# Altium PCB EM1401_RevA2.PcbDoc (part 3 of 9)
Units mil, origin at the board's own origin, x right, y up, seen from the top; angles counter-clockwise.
Board outline 7800 x 5300 mil, 6 copper layers (Top Layer, MidLayer1, MidLayer2, MidLayer3, MidLayer4, Bottom Layer), stack 16.8 mil thick; 751 components, 531 nets, 2554 pads, 1388 vias.
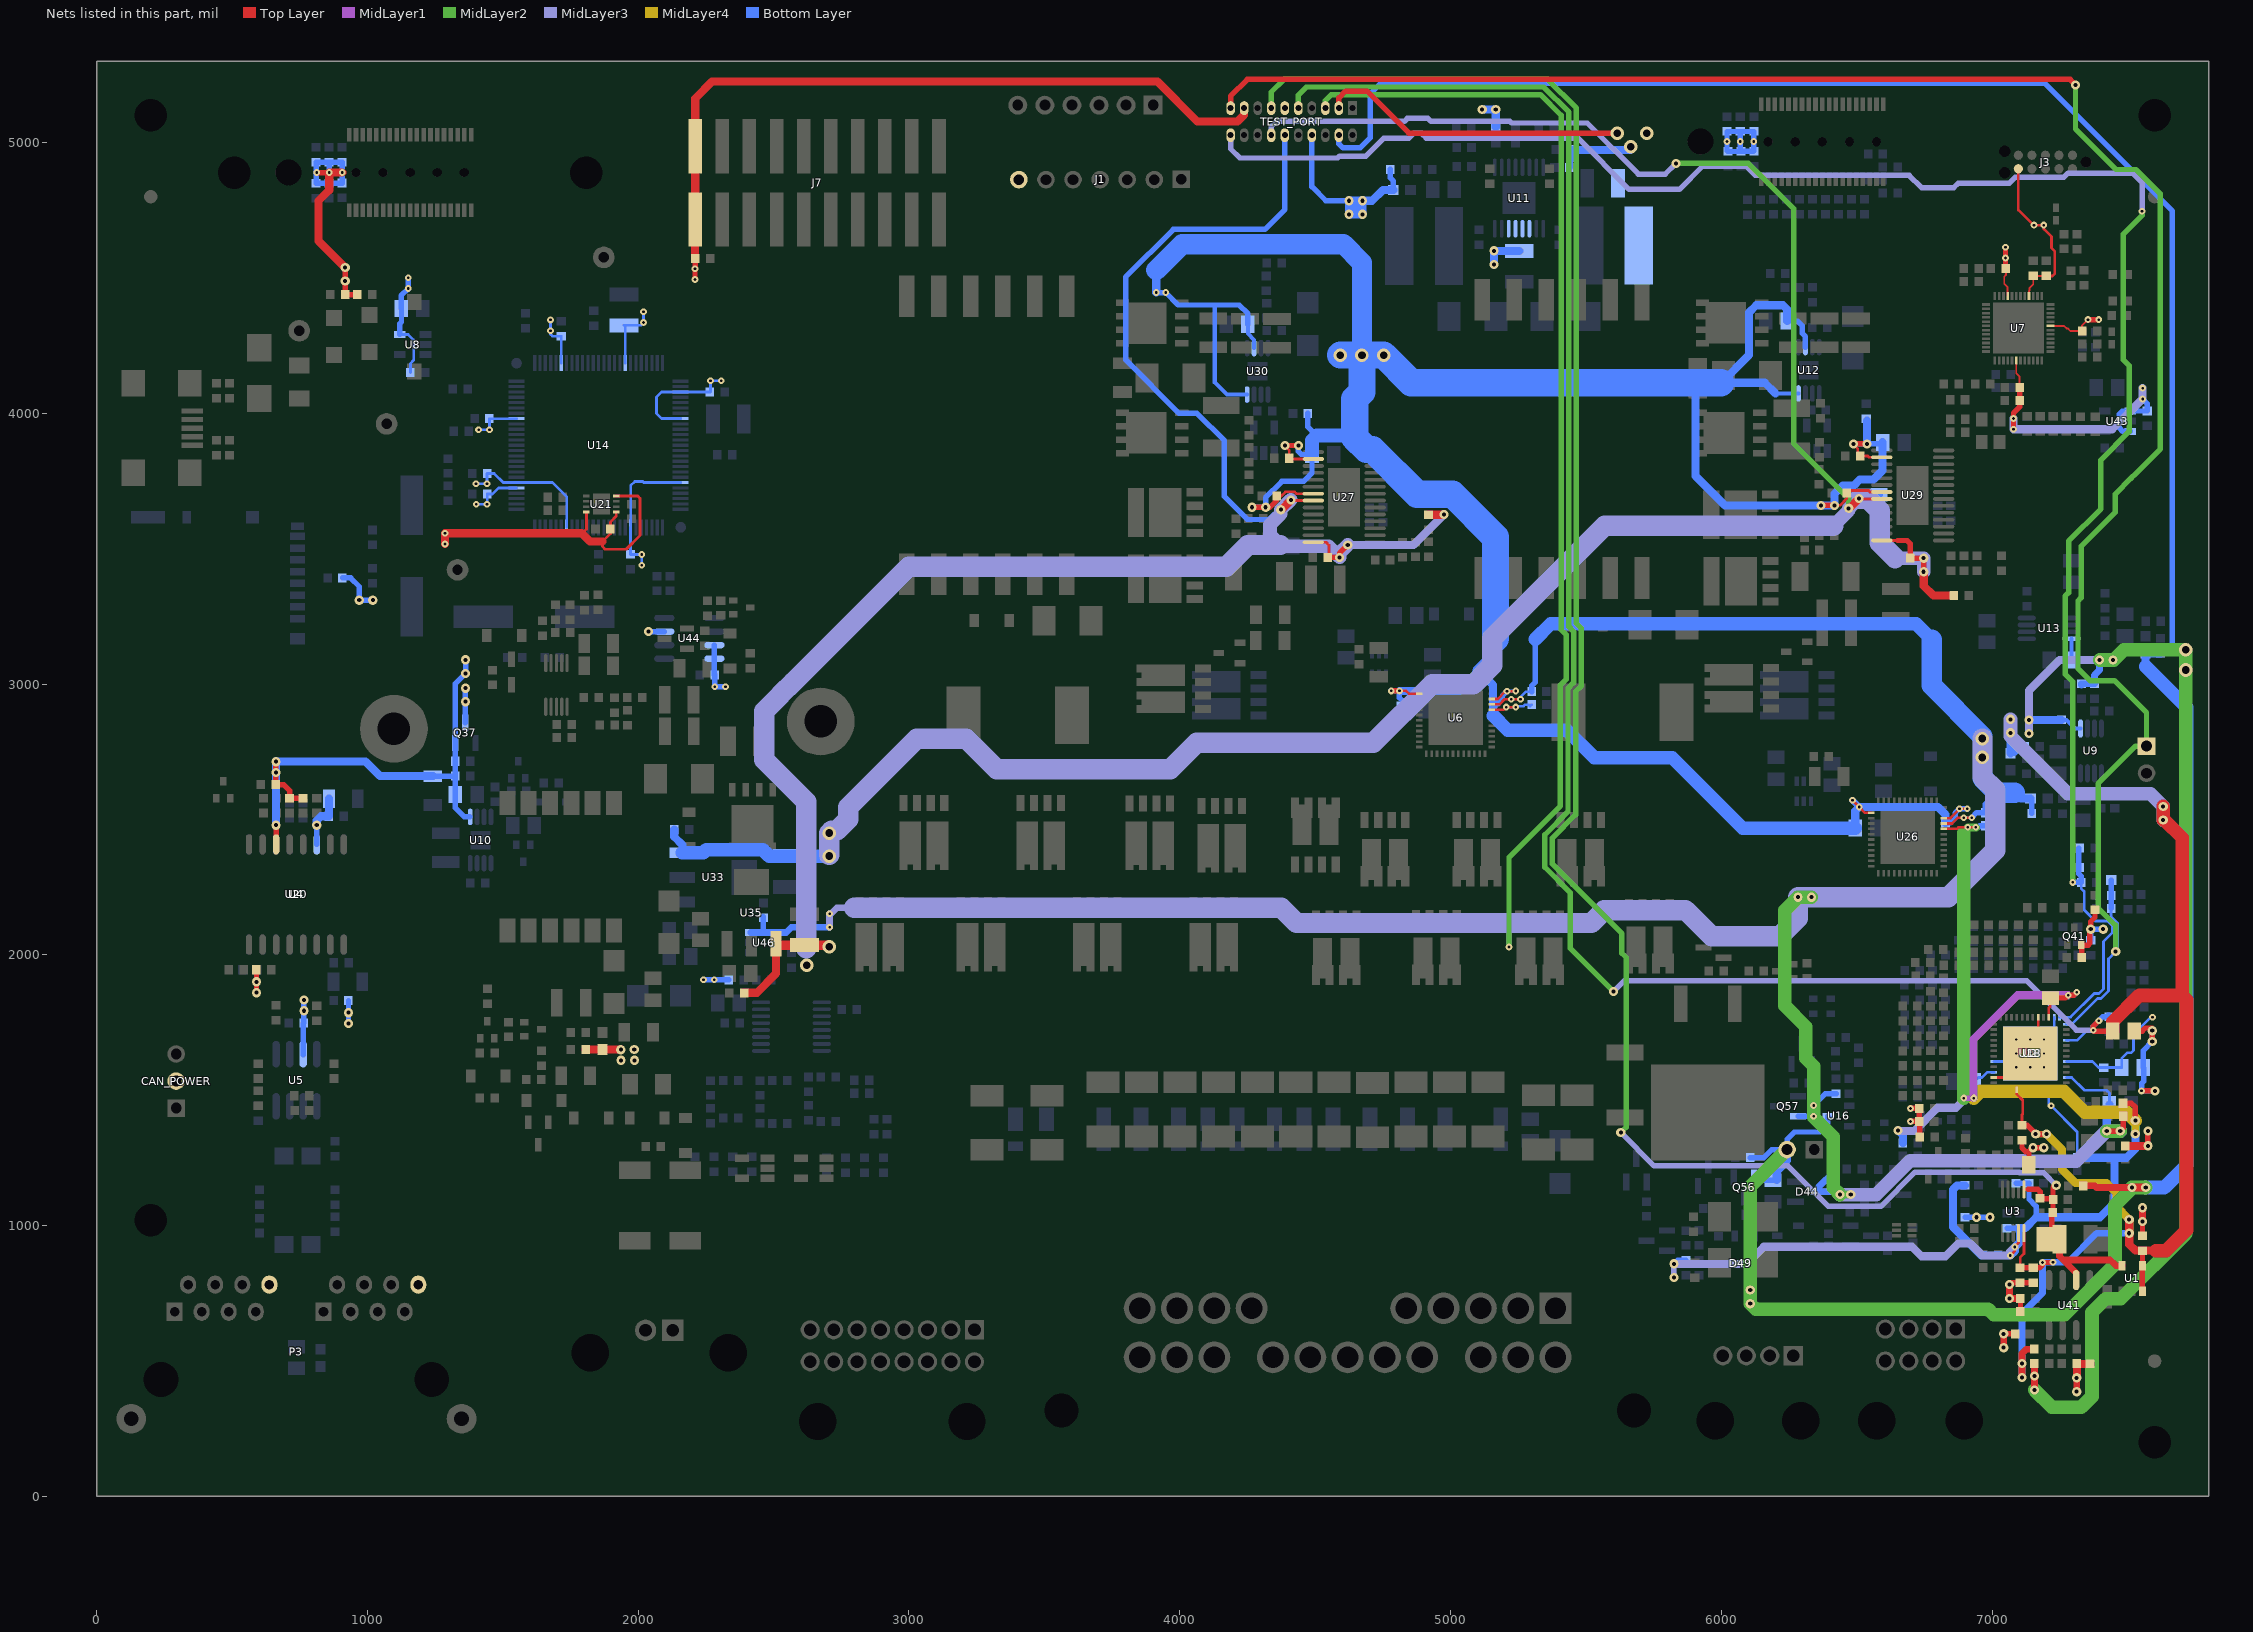
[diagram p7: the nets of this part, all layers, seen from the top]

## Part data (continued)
U21: "40MHz Dual Clock Buffer"
U24 U28: "IC INVERTER WITH SCHMITT TRIGGER SINGLE"
U27 U29: "PWM Controller"
U31: "8-Channel, 500 kSPS to 1 MSPS, 12-Bit A/D Converter"
U33 U35: "500 mA Low Dropout Regulator"
U34: "100V Current Mode PWM Controller"
U41: "IC PREC VREF 2.5V SOIC8"
U43: "Micropower 150 mA Low-Noise Ultra Low-Dropout Regulator, 5-pin SOT-23"
U44: library part 25LC512, "IC EEPROM 512KBIT 20MHZ"
Y1: library part "HC/49US - 4.194304MHz", "SMD Low Profile Crystal"
Y2: library part "HC/49US - 8MHz", "SMD Low Profile Crystal"
Zener1 Zener2: "Diode, Zener, 30V, 550mW, SMB"

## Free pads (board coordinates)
  round 50 smd: 0(7600,500) 1(200,4800) 2(7600,4800)

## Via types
v1: diameter 25, hole 10, Top Layer to Bottom Layer, tented both sides, 275 vias
v2: diameter 16, hole 8, Top Layer to Bottom Layer, tented both sides, 240 vias
v3: diameter 34, hole 15, Top Layer to Bottom Layer, tented both sides, 158 vias
v4: diameter 34, hole 15, Top Layer to Bottom Layer, 154 vias
v5: diameter 34, hole 15, Top Layer to Bottom Layer, tented top, 95 vias
v6: diameter 34, hole 15, Top Layer to Bottom Layer, tented bottom, 89 vias
v7: diameter 25, hole 10, Top Layer to Bottom Layer, tented bottom, 75 vias
v8: diameter 25, hole 10, Top Layer to Bottom Layer, 62 vias
v9: diameter 28, hole 8, Top Layer to Bottom Layer, tented both sides, 60 vias
v10: diameter 24, hole 8, Top Layer to Bottom Layer, 53 vias
v11: diameter 25, hole 10, Top Layer to Bottom Layer, tented top, 28 vias
v12: diameter 50, hole 28, Top Layer to Bottom Layer, 28 vias
v13: diameter 25, hole 8, Top Layer to Bottom Layer, tented both sides, 18 vias
v14: diameter 50, hole 28, Top Layer to Bottom Layer, tented top, 12 vias
v15: diameter 25, hole 8, Top Layer to Bottom Layer, tented top, 9 vias
v16: diameter 20, hole 8, Top Layer to Bottom Layer, tented both sides, 9 vias
v17: diameter 24, hole 8, Top Layer to Bottom Layer, tented bottom, 4 vias
v18: diameter 24, hole 8, Top Layer to Bottom Layer, tented top, 4 vias
v19: diameter 28, hole 10, Top Layer to Bottom Layer, tented both sides, 3 vias
v20: diameter 35, hole 14, Top Layer to Bottom Layer, 3 vias
v21: diameter 50, hole 28, Top Layer to Bottom Layer, tented both sides, 2 vias
v22: diameter 50, hole 28, Top Layer to Bottom Layer, tented bottom, 2 vias
v23: diameter 30, hole 14, Top Layer to Bottom Layer, tented top, 2 vias
v24: diameter 28, hole 10, Top Layer to Bottom Layer, 1 vias
v25: diameter 35, hole 14, Top Layer to Bottom Layer, tented both sides, 1 vias
v26: diameter 35, hole 14, Top Layer to Bottom Layer, tented top, 1 vias

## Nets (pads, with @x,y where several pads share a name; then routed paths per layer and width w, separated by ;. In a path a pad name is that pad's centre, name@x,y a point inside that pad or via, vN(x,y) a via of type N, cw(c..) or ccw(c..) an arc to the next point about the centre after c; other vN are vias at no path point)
+3V3: C1.2 C6.1 C15.2 C19.2 C40.2 C50.2 C63.1 C68.2 C80.2 C89.2 C99.2 C103.2 C111.2 C112.2 C115.2 C120.2 C201.2 C202.2 C203.2 C204.2 C214.2 C236.1 J1.7 J3.6 L8.2 Q37.3 R24.2 R47.2 R50.1 R51.2 R52.2 R81.1 R84.1 R104.1 R115.1 R117.1 R119.1 R121.1 R154.1 R193.1 R200.1 R209.1 R225.1 R234.1 TEST_PORT.8 U2.3 U3.9 U4.14 U6.32 U7.6 U7.19 U7.28 U7.33 U18.3 U18.38 U18.39 U18.40 U21.1 U21.4 U21.8 U26.32 U43.1 U43.3 | length 13743.6
  Top Layer w7: C203.2@7050.56,4534 7051,4533.56 7051,4511 7045,4505 7045,4478 7057.63,4465.37 U7.33@7057.63,4434.09 U7.33@7058,4434.46 ; U7.6@7089.13,4195.91 7089.13,4147.87 7101.56,4135.44 C201.2@7101.56,4095 ; C40.2@7101.56,4047.44 C40.2@7102,4047 ; U7.28@7136,4434.09 7136,4451.36 7138,4453.36 7138,4462.61 7152,4476.61 C214.2@7152,4508 7152.56,4507.44 C204.2@7200,4507.44 ; U7.19@7216.09,4322.87 7216.72,4322.24 7266.06,4322.24 7275.06,4313.24 7279.97,4313.24 7289.21,4304 C202.2@7332.44,4304 7332.44,4324.44 v1(7354,4346)
  Top Layer w10: 1792.44,3555.56 1808.88,3572.01 U21.8@1808.88,3635.47 ; U21.1@1919.12,3635.47 1919.12,3620.12 1897.56,3598.56 C115.2@1897.56,3573 1897.56,3555.56 1868,3526 1868,3508 1878,3498 1956,3498 2007,3549 2007,3686 1998.47,3694.53 U21.4@1919.12,3694.53 ; U6.32@5152.77,2905.77 5196.77,2905.77 v8(5206,2915) v1(5241,2915) ; U26.32@6821.77,2465.53 6870.53,2465.53 6876,2471 v1(6910,2471) v1(6940,2471) ; v1(7067,890) 7084,907 v1(7084,921) 7084,922 7097.89,935.89 U3.9@7097.89,972.42 ; J3.6@7097,4903 7097,4750.46 7152.46,4695 v1(7155,4695) v1(7191,4695) 7191,4681 7219.5,4652.5 7219.5,4610.17 7231,4598.67 7231,4515 7223.44,4507.44 C204.2@7200,4507.44 ; U2.3@7209.59,1769.78 7209.59,1803.59 7215,1809 7215,1840.24 C1.2@7215.41,1840.65
  Top Layer w20: v1(813,4889) v1(859,4889) ; v4(918,4539) v4(918,4489) R47.2@918,4438 R52.2@962.88,4438 ; v1@7049,4573.56 7049.56,4573 C203.2@7049.56,4534 ; v1(7049.56,4573.56) v1(7049.56,4613.56) ; v1(7079,3941) v1(7079,3981) 7079,4001 7102,4024 C40.2@7102,4047 ; C40.2@7101.56,4047.44 C201.2@7101.56,4095 ; C1.2@7215.41,1840.65 7270.65,1840.65 v1(7281,1851) 7302,1851 v1(7313,1862) ; v1(7354,4346) v1(7394,4346) ; R50.1@7483.53,1452 7514.82,1452 7529,1437.82 v3(7529,1388)
  Top Layer w30: v1(907,4889) v1(859,4889) 859,4824 820,4785 820,4637 v4(918,4539) ; v1(1287,3517) v1(1287,3557) 1791,3557 1792.44,3555.56 1822,3526 1868,3526
  MidLayer2 w20: v1(6895,1471) v1(6932,1471)
  MidLayer2 w30: 6895,2451 6910,2466 v1(6910,2471) v1(6940,2471)
  MidLayer2 w50: v1(6895,1471) 6895,2451
  MidLayer3 w20: v3(5825,809) v3(5825,859) ; v1(6895,1471) v1(6932,1471)
  MidLayer3 w30: v3(5825,859) 6094,859 6157,922 6704,922 6739,887 6828,887 6875,934 6921,934 6965,890 v1(7067,890) 7067,904 v1(7084,921) ; v3(6653,1351) 6654.5,1349.5 6713.12,1349.5 6799.12,1435.5 6866.12,1435.5 6895,1464.38 v1(6895,1471) ; v1(7079,3981) v1(7079,3941) 7444,3941 v1(7556,4053) v1(7556,4093)
  MidLayer4 w30: v1(6895,1471) v1(6932,1471) ; v3(7529,1338) v3(7529,1388)
  MidLayer4 w50: v1(6932,1471) 6957,1496 7265,1496 7342,1419 7498,1419 v3(7529,1388)
  MidLayer1 w20: v1(6895,1471) v1(6932,1471) ; v1(7281,1851) 7302,1851 v1(7313,1862)
  MidLayer1 w30: v1(6932,1471) 6932,1688.52 7094.48,1851 v1(7281,1851)
  Bottom Layer w10: v8(5206,2915) v1(5241,2915) 5244.5,2918.5 5269.5,2918.5 5275,2924 5288.42,2924 5293.92,2918.5 C19.2@5299.42,2924 ; v8@5209,2918 v8@5209.5,2918.5 ; v1(6910,2471) v1(6940,2471) ; C68.2@6934.42,1533 6948.87,1547.46 6963,1547.46 6982.57,1567.03 U18.3@7006.84,1567.03 ; U18.40@7189.91,1502.07 U18.39@7209.59,1502.07 ; U18.38@7229.28,1502.07 U18.39@7209.59,1502.07 ; R121.1@7314.12,1251 7314.12,1346.88 v11(7218,1443) 7209.59,1451.41 U18.39@7209.59,1502.07
  Bottom Layer w20: U4.14@813,2408.04 v5(813,2479) ; C63.1@908,3392 938,3392 970,3360 v3(970,3310) v3(1020,3310) ; v3@1359.6,2987.4 v3(1362,2985) v3(1362,2935) Q37.3@1362,2857.4 ; v8(2241,1908) v8(2281,1908) R104.1@2335.3,1908 ; TEST_PORT.8@4488,5027 4488,4837 4540,4785 v4(4625,4785) ; C89.2@4777.79,4901 4777.79,4869.21 4789.01,4857.99 L8.2@4789.01,4825 ; v3(5825,809) v3(5825,859) 5838.14,872.14 R51.2@5869.53,872.14 ; C111.2@6021,4969.12 v1(6021,5004) C112.2@6021,5040.88 R225.1@6070,5040.88 ; C111.2@6024,4967 6071.88,4967 R209.1@6072,4967.12 ; v1(6895,1471) v1(6932,1471) ; v1@6933,1472 v1(6932,1471) ; C68.2@6934.74,1532.68 C68.2@6934.42,1533 6932,1530.58 v1(6932,1471) ; v1(6940,2471) 6949,2471 6955,2477 C120.2@6974.29,2476.98 ; C6.1@7055,991 C236.1@7103,991 ; R117.1@7088.42,1156.88 7136.3,1156.88 R119.1@7136.42,1157 ; R119.1@7137.73,1155.68 R119.1@7136.42,1157 ; 7163,1031 7163,1071 7136.42,1097.58 R119.1@7136.42,1157 ; U43.3@7510.24,3933.6 7482.4,3933.6 7470,3946 7470,3997 7481.4,4008.4 U43.1@7510.24,4008.4 7510.4,4008.56 C99.2@7573,4008.56 7573,4036 v1(7556,4053) v1(7556,4093) ; R84.1@859,4850.12 906.56,4850.12 R81.1@907,4850.56 v1(907,4889) R193.1@907,4926.88 R154.1@859,4926.88 ; R84.1@859,4850.12 858.88,4850 C103.2@811,4850 811,4887 v1(813,4889) 811,4889 C50.2@811,4927 858.88,4927 R154.1@859,4926.88 ; R84.1@859,4850.12 v1(859,4889) R154.1@859,4926.88 ; R225.1@6070,5040.88 v1(6070,5004) 6070,4969.12 R209.1@6072,4967.12 ; R225.1@6070,5040.88 R234.1@6120,5040.88 v1(6120,5004) 6120,4969.12 6118,4967.12 R209.1@6072,4967.12
  Bottom Layer w30: v5(813,2479) 813,2496 829,2512 C80.2@858,2512 C15.2@858,2577 ; L8.2@4789.01,4825 4750,4825 4710,4785 v4(4675,4785) ; v3(6653,1351) 6655,1351 6670.88,1335.12 R24.2@6670.88,1305 ; R115.1@6900.42,1148.88 6870.88,1148.88 6855.42,1133.42 6855.42,1004.43 6855.15,1004.16 6855.15,994.85 6960,890 v1(7067,890) 7084,907 v1(7084,921) 7103,940 C236.1@7103,991 7123,991 7163,1031 7399,1031 7452,1084 7452,1250 7453,1251 ; R121.1@7314.12,1251 7453,1251 ; v3(7529,1388) v3(7529,1338) 7529,1284 7496,1251 7453,1251 ; 4625,4760 4675,4760 ; 4625,4760 v4(4625,4785) v4(4675,4785) ; 4625,4760 v4(4625,4735) v4(4675,4735) 4675,4760 ; 4675,4760 v4(4675,4785)
+3V3_LP: C29.1 C30.1 C31.1 C32.1 C33.2 C36.1 C41.1 C43.2 C44.2 C58.1 C60.1 C229.2 J7.1 J7.2 Q37.2 R44.1 R65.1 R67.1 R150.2 R151.1 R159.1 TEST_PORT.17 U8.5 U10.1 U14.3 U14.8 U14.20 U14.32 U14.44 U14.55 U14.56 U14.68 U14.81 U14.93 U20.14 U44.3 U44.7 U44.8 | length 7647.1
  Top Layer w10: v11(2209.88,4534) v11@2210.44,4534.56
  Top Layer w20: v5(662.12,2713.56) v5(662.12,2673.56) R67.1@662.12,2629 690.5,2629 713,2606.5 R151.1@713,2579.12 R159.1@763,2579.12 ; U20.14@663,2408.04 v5(663,2479) ; v1(1151,4461) v1@1151,4462 ; v11(2209.88,4494) v11(2209.88,4534) ; v11@2210.44,4534.56 C33.2@2210.44,4572
  Top Layer w30: C33.2@2210.44,4572 2210.44,4715.44 J7.1@2211,4716 J7.2@2211,4986 2211,5163 2273,5225 3917.53,5225 4064.53,5078 4214,5078 4238,5102 TEST_PORT.17@4238,5127
  Bottom Layer w10: U8.5@1119.76,4291.4 1150.6,4291.4 1171,4271 1171,4196 1159,4184 R65.1@1159,4151 ; v7(1401.44,3740) v7(1441.44,3740) 1442,3740.56 C43.2@1442,3778 1468,3778 1501.8,3744.2 U14.56@1550.85,3744.2 1683.8,3744.2 1735.89,3692.11 U14.44@1735.89,3578.85 ; v7(1402,3664) v7(1442,3664) 1442.56,3664.56 C29.1@1442.56,3702 1461.54,3702 1484.06,3724.52 U14.55@1550.85,3724.52 ; v7(1410.85,3939.43) v7(1450.85,3939.43) C44.2@1450.85,3980.43 U14.68@1550.85,3980.43 ; v1(1676,4345) v1(1676,4305) 1676,4292 1683,4285 C31.1@1716,4285 1716.2,4284.8 U14.81@1716.2,4185.15 ; C41.1@1947,4324.91 C41.1@1948,4324.91 C41.1@1952.43,4324.91 ; U14.93@1952.43,4185.15 C41.1@1952.43,4324.91 ; v1(2013,3438.85) v1(2013,3478.85) C36.1@1972,3478.85 1972,3578.74 U14.32@1972.11,3578.85 1972.11,3733.05 1987.56,3748.5 2016.56,3748.5 2020.86,3744.2 U14.20@2157.15,3744.2 ; v7(2020,4375) v7(2020,4335) 2009.91,4324.91 C41.1@1952.43,4324.91 ; U14.8@2157.15,3980.43 2157.07,3980.5 2086.5,3980.5 2068,3999 2068,4060 2086.85,4078.85 U14.3@2157.15,4078.85 C30.1@2264,4078.85 2267.15,4078.85 v7(2267.15,4119.85) v7(2307.15,4119.85)
  Bottom Layer w20: U8.5@1119.76,4291.4 1119.76,4331.76 1126,4338 1126,4386 C32.1@1125,4387 1125,4435 v1(1151,4461) v1(1151,4501) ; C60.1@1242,2660 R150.2@1325,2660 ; v3@1362,3039 1324.6,3001.6 Q37.2@1324.6,2782.6 1324.6,2715.4 R44.1@1325,2715 R150.2@1325,2660 ; v3(1362.6,3039.6) v3(1362.6,3089.6) ; U10.1@1378.35,2510.66 1357.34,2510.66 1325,2543 C58.1@1325,2592 R150.2@1325,2660 ; v3(2038,3194) U44.3@2096.48,3194 ; U44.7@2281.52,3144 U44.8@2281.52,3094 2281.52,3035.04 C229.2@2282.56,3034 v1(2282.56,2990) v1(2322.56,2990)
  Bottom Layer w30: v5(663,2479) 662.12,2479.88 v5(662.12,2673.56) v5(662.12,2713.56) 993.44,2713.56 1047,2660 C60.1@1242,2660 ; v3@1362,3039 v3(1362.6,3039.6)
+5V5: C52.1 C93.1 C97.1 C105.1 L10.2 R64.1 R100.1 R246.2 R249.2 TEST_PORT.3 U9.1 U13.8 | length 6234.1
  Top Layer w20: TEST_PORT.3@4588,5127 4588,5165 4613,5190 4691,5190 4846,5035 v12(5615,5035)
  Top Layer w25: R100.1@7155.86,491 7156.98,489.88 v3(7156.98,444.68) v3(7156.98,393.5)
  MidLayer2 w25: v3(7156.98,393.5) v3(7156.98,444.68)
  MidLayer2 w50: v3(7156.98,393.5) 7220.47,330 7330,330 7369,369 7369,680 7419,730 7475.42,730 7715,969.58 v12(7715,3052) v12(7715,3127) 7487.1,3127 v6@7448.66,3088.57 ; v6(7397,3089) v6(7447,3089)
  MidLayer3 w30: v6(7136.44,2817.56) v6(7136.44,2867.56) 7136.44,2976.44 7248.57,3088.57 v6(7397,3089) v6@7440.98,3088.57
  Bottom Layer w15: C105.1@7257,2867.56 7275.44,2867.56 7307,2836 U9.1@7326.82,2836 ; C52.1@7290.64,3088.57 7293.36,3091.29 U13.8@7293.36,3167.38
  Bottom Layer w25: R64.1@5439.12,4908 5439.12,4931.12 5447.5,4939.5 C97.1@5447.5,4973 ; R246.2@7330,2996.56 R246.2@7330.44,2997 ; R246.2@7330,3000.56 7330.44,3001 R249.2@7378,3001 7378,3033 7397,3052 v6(7397,3089)
  Bottom Layer w30: C97.1@5447.5,4973 v12@5665,4973 ; v6(7136.44,2817.56) v6(7136.44,2867.56) C105.1@7257,2867.56 ; C52.1@7290.64,3088.57 v6(7397,3089) v6@7440.98,3088.57
  other v12: 5665,4985 5725,5035
+5V_1: C2.1 C7.1 C9.1 C71.1 C87.2 C237.1 L6.2 R131.1 R235.2 TEST_PORT.9 U1.3 U1.4 U2.28 U3.10 U18.28 | length 12219.1
  Top Layer w10: U2.28@7091.48,1502.07 7091.48,1484.94 7113.35,1463.06 7113.35,1412.94 7110.41,1410 C9.1@7110.41,1370.65 ; C7.1@7103.83,844 7103.83,882.83 7117.58,896.58 U3.10@7117.58,972.42
  Top Layer w20: C7.1@7103.83,844 7151.91,844 C237.1@7152.07,843.84 7174.84,843.84 7185.84,854.84 v1(7185.84,863.84) 7225.84,863.84 v1(7224.67,865) ; C9.1@7110.41,1370.65 7130.76,1370.65 7161.09,1340.33 v3(7161.09,1338) v3(7201.09,1338) ; v1(7394.42,1757) 7373.42,1736 v11(7373.42,1722) 7376.76,1718.65 C71.1@7445.41,1718.65 ; U1.3@7554.82,757.76 U1.4@7554.82,852.24 7555.42,852.84 C2.1@7555.42,908
  Top Layer w25: v3(7110.53,439.5) v3(7110.53,490.68) 7110.53,528.12 7126.42,544 R235.2@7155.86,544
  Top Layer w30: v5(7506.42,1023.06) v3(7506.42,971.88) 7506.42,931 7529.42,908 C2.1@7555.42,908 7605.42,908
  Top Layer w50: C71.1@7445.41,1718.65 7445.41,1752.6 7542.81,1850 7702,1850 ; 7605.42,908 7643.42,908 7718,982.58 7718,1834 7702,1850 ; v6(7632,2548) v6(7632,2498) 7636.35,2498 7702,2432.35 7702,1850
  MidLayer2 w20: TEST_PORT.9@4438,5127 4438,5175 4468,5205 5344,5205 5437,5112 5437,3212.12 5455,3194.12 5455,3005.42 5434,2984.42 5434,2529.18 5348,2443.18 5348,2323.97 5442,2229.97 5442,2025 v4(5602,1865)
  MidLayer3 w20: v4(5602,1865) 5641,1904 7129,1904 7311,1722 v11(7373.42,1722)
  MidLayer3 w50: v6(7068,2870) v6(7068,2820) 7068,2807 7280,2595 7585,2595 v6(7632,2548) v6(7632,2498)
  MidLayer4 w25: v3(7161.09,1338) v3(7201.09,1338)
  MidLayer4 w30: v3(7201.09,1338) 7258,1281.09 7258,1208 7308,1158 7422,1158 7459,1121 7459,1070.48 v5(7506.42,1023.06) v3(7506.42,971.88)
  Bottom Layer w10: U18.28@7274.55,1685.14 7314.89,1685.14 7351.76,1722 v11(7373.42,1722)
  Bottom Layer w20: L6.2@7068,2744.5 7082.5,2744.5 7108,2770 C87.2@7121,2770 ; v11(7373.42,1722) 7373.42,1736 v1(7394.42,1757) 7409.19,1771.77 R131.1@7431.41,1771.77 ; R131.1@7428.19,1776.77 R131.1@7431.41,1776.77
  Bottom Layer w25: v3(7110.53,439.5) v3(7110.53,490.68) 7110.53,676.12 7185.84,751.42 v1(7185.84,863.84) 7187,865 v1(7224.67,865) 7279.42,865 7386.3,971.88 v3(7506.42,971.88) v5(7506.42,1023.06)
  Bottom Layer w30: L6.2@7068,2744.5 v6(7068,2820) v6(7068,2870)
+5V_CAN: C81.2 CAN_POWER.2 P3.A8 P3.B8 R21.1 R95.2 U5.3 | length 368.6
  Top Layer w20: v3(590.44,1860.44) v3(590.44,1900.44) R95.2@590.44,1945
  Bottom Layer w20: U5.3@763,1631.49 U5.3@763,1633.46 C81.2@763,1746.44 ; C81.2@765.56,1749 v6(765.56,1793.56) v6(765.56,1833.56) ; v6(930.12,1746.44) v6(930.12,1786.44) R21.1@930.12,1831
+5VD: C18.2 C20.2 C72.1 C119.2 C239.1 D44.3 L9.1 Q57.2 R271.2 R274.1 R278.1 TEST_PORT.5 U6.33 U18.35 U26.33 U46.3 U46.4 | length 16088.4
  Top Layer w10: U6.33@5152.77,2925.46 5180.39,2925.46 5198.94,2944 v1(5224.42,2944) v1(5258.42,2944) ; U26.33@6821.77,2485.21 6852.57,2485.21 6874.13,2506.78 v1(6894.98,2506.78) v1(6924.98,2506.78)
  Top Layer w20: v3@7433.42,1349.33 v3(7473.42,1349.33) 7484.98,1360.89 R271.2@7484.98,1404
  MidLayer2 w20: TEST_PORT.5@4538,5127 4538,5155 4560,5177 5332,5177 5409,5100 5409,3200.53 5427,3182.53 5427,3017.02 5406,2996.02 5406,2550 5216,2360 v11(5216,2029)
  MidLayer2 w30: v3(6438,1115) v3(6478,1115)
  MidLayer2 w50: v6(6333,2213) v6(6283,2213) 6235,2165 6235,1812 6312,1735 6312,1618 6341,1589 v7(6341,1444) v7(6341,1404) 6341,1400 6413,1328 6413,1140 v3(6438,1115) ; v3(7423.42,1349.33) v3(7473.42,1349.33)
  MidLayer3 w20: 5215,2118 5216,2117 v11(5216,2029)
  MidLayer3 w25: v11(2707,2102) v11(2707,2152) 2712.76,2152 2734.76,2174 2797,2174
  MidLayer3 w50: v3(6438,1115) v3(6478,1115) 6572,1115 6697.5,1240.5 7117.91,1240.5 7120.41,1238 7311.29,1238 7422.62,1349.33 v3(7423.42,1349.33) v3(7473.42,1349.33)
  MidLayer3 w75: 2797,2174 4375,2174 4431,2118 5215,2118 5521,2118 5568,2165 5868,2165 5964.5,2068.5 6216.5,2068.5 6283,2135 v6(6283,2213) v6(6333,2213) 6839,2213 7012,2386 7012,2609 6964.42,2656.58 v22(6964.42,2729) v22(6964.42,2799)
  Bottom Layer w10: v1(5258.42,2944) 5255.42,2944 5255.42,2949 5278.42,2972 C18.2@5299.3,2972 ; v1(6894.98,2506.78) v1(6924.98,2506.78) ; U18.35@7274.55,1547.34 7294.07,1547.34 7341.28,1500.13 7423.07,1500.13 7433.41,1489.79 C72.1@7433.41,1447.65
  Bottom Layer w20: 2462.36,2082.8 C239.1@2462.36,2140.44 ; C18.2@5299.3,2972 5299.3,2993.3 5312.42,3006.42 5312.42,3165 ; Q57.2@6283.8,1403.6 6340.6,1403.6 v7(6341,1404) v7(6341,1444) 6384.44,1487.44 R274.1@6424,1487.44 ; v1(6924.98,2506.78) 6943.18,2524.98 C119.2@6974.29,2524.98 6974.29,2555.88 7017.42,2599 ; L9.1@7142.01,2577 7146,2573.01 C20.2@7146,2522
  Bottom Layer w25: U46.3@2415.93,2082.8 2462.36,2082.8 U46.4@2510.42,2082.8 2546.8,2082.8 2566,2102 v11(2707,2102) v11(2707,2152) ; D44.3@6361.31,1125 D44.3@6361.31,1125.52 ; R278.1@6418,1226 6418,1201 6361.31,1144.31 D44.3@6361.31,1125.52 ; v3(6478,1115) v3(6438,1115) 6423,1115 6412.48,1125.52 D44.3@6361.31,1125.52
  Bottom Layer w30: 7084,2599 7106,2577 L9.1@7142.01,2577 ; C72.1@7433.41,1447.65 7433.41,1406 7423.42,1396 v3(7423.42,1349.33) v3(7473.42,1349.33)
  Bottom Layer w50: 5312.42,3165 5370.42,3223 6719,3223 6777,3165
  Bottom Layer w75: 6777,3165 6777,2994.98 6964.29,2807.68 6964.29,2652.12 7017.42,2599 7084,2599
+12V: C17.2 C42.1 C83.2 C118.2 C128.2 C130.1 C138.2 C140.1 C208.2 C210.2 C220.1 C222.1 C230.2 C231.2 L3.2 R63.1 R275.2 R277.2 TEST_PORT.11 U6.2 U6.34 U11.11 U11.12 U11.13 U11.14 U12.4 U12.6 U26.2 U26.34 U27.16 U27.21 U29.16 U29.21 U30.4 U30.6 | length 12912
  Top Layer w10: C128.2@4356.42,3693.44 4357.42,3694.44 4374.86,3694.44 4390.42,3710 4424.32,3710 4430.99,3703.33 U27.21@4493.28,3703.33 ; v3@4385.98,3881 4404.98,3862.01 C230.2@4404.98,3834 ; C230.2@4404.98,3826 C230.2@4405.42,3826.44 ; C230.2@4405.42,3831.28 U27.16@4493.28,3831.28 ; v1(4811.42,2975) 4836.42,2975 4846.59,2964.83 U6.2@4885.06,2964.83 ; U6.34@5152.77,2945.14 5174.62,2945.14 5203.48,2974 v1@5208.42,2974 ; v1(5208.57,2973.82) v1@5240.45,2973.82 ; v5(6418.42,3660) 6438.42,3660 6462.98,3684.56 C138.2@6462.98,3705 ; C138.2@6462.98,3708 C138.2@6462.98,3705 ; v1(6484.42,2571) v1(6509.42,2546) 6530.83,2524.58 U26.2@6554.06,2524.58 ; v5@6485.41,3887.15 6504.4,3868.16 C231.2@6504.4,3840.15 ; C231.2@6512.98,3842 6541.42,3842 6545.99,3837.43 U29.16@6592.7,3837.43 ; U29.21@6592.7,3709.47 6549.9,3709.47 6544.34,3715.03 6473.01,3715.03 C138.2@6462.98,3705 ; U26.34@6821.77,2504.9 6846.8,2504.9 6879.9,2538 v1@6881.42,2538 ; v1(6879.42,2540) v1(6908.42,2540)
  Top Layer w20: v5(4267.42,3653) v5(4317.42,3653) 4332.42,3653 4356.42,3677 C128.2@4356.42,3693.44 ; v3@4385.98,3881 v3(4388.42,3881) v3(4438.42,3881) ; v1(4781.42,2975) v1(4811.42,2975) ; v1@5240.45,2973.82 v1(5240.85,2974.22) ; v5(6368.42,3660) v5(6418.42,3660) ; v5@6485.41,3887.15 v5(6487.84,3887.15) v3(6537.84,3887.15)
  Top Layer w30: C83.2@1806.12,1651 1806.61,1650.5 L3.2@1868,1650.5 1935.5,1650.5 v3(1936,1650) ; v3@1936.5,1649.5 v3(1936,1650) ; v3@1936.5,1650.5 v3(1936,1650)
  Bottom Layer w10: v1@5208.97,2974.22 v1(5240.85,2974.22)
  Bottom Layer w15: 4129.42,4400 4129.42,4114.19 4174.23,4069.37 U30.4@4249.03,4069.37 ; C130.1@4251.42,4329 4251.42,4294 4274.62,4270.8 U30.6@4274.62,4240.63 ; 6200.05,4073.37 U12.4@6285.03,4073.37
  Bottom Layer w20: v1(3913.42,4446) v1(3948.42,4446) 3994.42,4400 4129.42,4400 4219.36,4400 4251.42,4367.95 C130.1@4251.42,4329 ; v5(4267.42,3653) v5(4317.42,3653) 4317.42,3689 4377.42,3749 4457.42,3749 4488.42,3780 C220.1@4488.42,3848 4449.42,3848 4438.42,3859 v3(4438.42,3881) v3(4388.42,3881) ; R275.2@4473.47,4000 4473.47,3949.94 4505.42,3918 ; v1(4781.42,2975) v1(4811.42,2975) 4811.42,2949.58 4825.92,2935.08 C208.2@4825.92,2904 ; C17.2@5157.48,2928 5175.87,2928 5192,2944.13 5192,2957.25 v1(5208.57,2973.82) ; C140.1@6243.42,4341 6281.42,4341 6299.42,4323 6299.42,4295 6310.62,4283.8 U12.6@6310.62,4244.63 ; v5(6487.84,3887.15) v3(6537.84,3887.15) 6589.56,3887.15 C222.1@6595.42,3893 ; C118.2@6827.98,2487 6846.42,2487 6863.42,2504 6863.42,2524 v1(6879.42,2540) v1(6908.42,2540)
  Bottom Layer w25: v1(6484.42,2571) v1(6509.42,2546)
  Bottom Layer w30: v1(3913.42,4446) 3913.42,4529 ; v1(4811.42,2975) 5032.42,2975 5105.92,3048.5 5157.48,2996.94 C17.2@5157.48,2928 5157.48,2883.94 ; v6(5117,5122) v6(5167,5122) R63.1@5167,5056.99 ; v4(5161,4550) v4(5161,4600) C42.1@5254,4600 ; 5905,4113 5905,3769 6014,3660 v5(6368.42,3660) v5(6418.42,3660) 6418.42,3703 6448.42,3733 6489.42,3733 6511.42,3755 6561.42,3755 6595.42,3789 C222.1@6595.42,3893 ; 5998,4113 6001,4113 ; 6200.05,4073.37 6160.42,4113 6001,4113 ; C140.1@6243.42,4341 6243.42,4384 6228.42,4399 6129,4399 6103,4373 6103,4215 6001,4113 ; C210.2@6494.85,2467.98 6494.85,2531.44 v1(6509.42,2546) 6800.53,2546 6827.98,2518.56 C118.2@6827.98,2487 ; R277.2@6537.42,3972.55 6537.42,3887.57 v3(6537.84,3887.15)
  Bottom Layer w50: C220.1@4488.42,3848 4488.42,3901 4505.42,3918 4646.42,3918 4673,3918 ; 5105.92,3048.5 5165.42,3108 5165.42,3169 ; 5157.48,2883.94 5211.42,2830 5429.42,2830 5531.42,2728 5819,2728 6079.02,2467.98 C210.2@6494.85,2467.98
  Bottom Layer w75: 3913.42,4529 4008.42,4624 4605,4624 4673,4556 4673,4221 v14@4667,4215
  Bottom Layer w100: v14(4593,4215) v14@4667,4215 ; 5165.42,3169 5165.42,3542.65 5007.07,3701 4877,3701 4712,3866 4690.35,3866 4646.42,3909.93 4646.42,3918 4646.42,4052.42 4673,4079 4673,4209 v14@4667,4215 ; 5998,4113 5905,4113 4855,4113 v14(4753,4215) v14(4673,4215) v14@4667,4215
  other v3: 1936.5,1610.5 1986.5,1610.5 1985.5,1650.5
+12VF1: C121.1 C165.1 C219.1 R218.2 R237.2 TEST_PORT.12 U27.22 U27.28 U35.3 | length 7246
  Top Layer w10: v5(4373.42,3644) v5@4375.42,3644 ; v5(4411.42,3680) 4413.68,3677.74 U27.22@4493.28,3677.74 ; U27.28@4493.28,3524.19 4539.22,3524.19 4550.98,3512.44 4550.98,3468 C121.1@4550.98,3465
  Top Layer w20: C121.1@4550.98,3468 v5(4590.42,3468) 4590.42,3484 v5(4620.42,3514)
  Top Layer w30: R218.2@2390.97,1860 2438.42,1860 2508.97,1930.55 U35.3@2508.97,2040.83 ; v5@4375.42,3644 v5(4411.42,3680) ; R237.2@4919,3625.56 4975.56,3625.56 v5(4976,3626)
  Top Layer w35: U35.3@2508.97,2040.83 2513.73,2036.06 C165.1@2614.42,2036.06 2706.35,2036.06 v21@2706.42,2036
  MidLayer3 w30: v5@4409.42,3680 v5(4411.42,3680) ; v5(4620.42,3514) 4864,3514 v5(4976,3626)
  MidLayer3 w50: v5@4409.42,3680 v5(4373.42,3644) 4373.42,3628.42 4333.42,3588.42 4333.42,3551 4370.99,3513.43 4375.42,3509 4549.42,3509 v5(4590.42,3468) 4590.42,3484 v5(4620.42,3514)
  MidLayer3 w75: 2620.42,2025 2620.42,2565 2465.42,2720 2465.42,2900 2528.55,2963.14 2528.55,2963.98 2572.08,3007.51 2572.92,3007.51 2998.92,3433.5 4171.5,3433.5 4251.43,3513.43 4370.99,3513.43
  Bottom Layer w20: 4337.42,3608 4250,3608 4165,3693 4165,3898.75 4063.75,4000 3998,4000 3800,4198 3800,4503 3976.5,4679.5 4314.5,4679.5 4388,4753 TEST_PORT.12@4388,5027
  Bottom Layer w30: C219.1@4337.42,3510 4337.42,3608 v5(4373.42,3644) 4375.42,3644 v5(4411.42,3680)
  other v21: 2622,1961 2706.42,2030
+12VF2: C131.1 C159.1 C221.1 R213.2 R238.2 TEST_PORT.14 U29.22 U29.28 U33.3 | length 9861.3
  Top Layer w10: v5(6508.45,3685.03) 6509.6,3683.88 U29.22@6592.7,3683.88 ; U29.28@6592.7,3530.34 6651.08,3530.34
  Top Layer w20: 6651.08,3530.34 6686.08,3530.34 6697.48,3518.94 C131.1@6697.48,3465 v5(6747.48,3465) v5(6747.48,3415)
  Top Layer w30: v5(6470.45,3649.03) 6472.45,3649.03 v5(6508.45,3685.03) ; v5(6747.48,3415) 6747.48,3362.94 6783.42,3327 R238.2@6854.42,3327
  MidLayer2 w20: v4(5833,4923) 6100,4923 6267.42,4755.58 6267.42,3889 6470.45,3685.97 v5(6470.45,3649.03)
  MidLayer3 w20: TEST_PORT.14@4338,5027 4338,5060 4356,5078 4829.31,5078 4840.91,5089.6 4916.29,5089.6 4927.89,5078 5219.49,5078 5225.5,5071.99 5505.01,5071.99 5694,4883 5793,4883 v4(5833,4923)
  MidLayer3 w30: v5(6470.45,3649.03) 6506.45,3685.03 v5(6508.45,3685.03)
  MidLayer3 w50: 6414.13,3585 6470.45,3641.32 v5(6470.45,3649.03) 6472.45,3649.03 v5(6508.45,3685.03) ; 6641.8,3465 v5(6747.48,3465) v5(6747.48,3415)
  MidLayer3 w75: v12@2705.42,2370 v12(2705.42,2450) 2714.92,2459.5 2734.62,2459.5 2775.92,2500.8 2775.92,2545.92 3028,2798 3212,2798 3324.5,2685.5 3965.5,2685.5 4063,2783 4715,2783 4932,3000 5085,3000 5154,3069 5154,3170 5569,3585 6414.13,3585 ; v5(6508.45,3685.03) 6540.38,3685.03 6585.42,3640 6585.42,3521.39 6641.8,3465
  Bottom Layer w30: R213.2@2133.3,2463 2133.3,2436.12 2163.42,2406 U33.3@2163.42,2376.55 ; v5(6470.45,3649.03) 6472.45,3649.03 v5(6508.45,3685.03) 6523.42,3700 C221.1@6582.42,3700
  Bottom Layer w50: U33.3@2163.42,2376.55 2239.97,2376.55 2252.42,2389 2459.42,2389 2483.33,2365.09 C159.1@2550.42,2365.09 v12(2705.42,2365.09) ; v12@2705.42,2370 v12(2705.42,2450)
+VREF: C3.1 C64.2 C228.1 C248.1 R30.1 TEST_PORT.13 U1.5 U3.1 U41.6 | length 7738
  Top Layer w10: U3.1@7117.58,1133.84 7132.58,1133.84
  Top Layer w20: 7132.58,1133.84 7169.58,1133.84 7177.42,1126 R30.1@7177.42,1102 7189.42,1102 R30.1@7192.42,1099 ; 7197.42,1099 7222.07,1099 C3.1@7225.07,1096 ; C248.1@7211.86,954.06 7213.91,952 7219.86,957.94 C228.1@7219.86,1050 ; C228.1@7224.86,1049.79 7225.07,1050 C3.1@7225.07,1096 ; v3(7237,1149) 7234,1149 7225.07,1140.07 C3.1@7225.07,1096 ; U41.6@7310.41,799.17 U41.6@7310.41,826
  Top Layer w25: C64.2@7249.42,952 C64.2@7249.42,950 7249.42,887 U41.6@7310.41,826 ; 7269.42,873 7436.42,873 7457.17,852.24 U1.5@7480.01,852.24
  MidLayer2 w20: TEST_PORT.13@4338,5127 4338,5186 4385,5233 5359,5233 5465,5127 5465,3223.72 5483,3205.72 5483,2993.82 5462,2972.82 5462,2517.58 5376,2431.58 5376,2335.57 5633,2078.57 5633,2006 5649,1990 5649,1364 v3(5629,1344)
  MidLayer3 w20: v3(5629,1344) 5752,1221 6245.55,1221 6395.55,1071 6589,1071 6715.5,1197.5 7100.1,1197.5 7102.6,1195 7191,1195 v3(7237,1149)
-5V1: C16.1 C85.2 D49.1 D49.2 L4.2 PING_OFF.2 Q56.2 R20.1 R273.2 TEST_PORT.4 U16.3 | length 10866.6
  Top Layer w25: R20.1@7336.98,1147 7380.04,1147 7386.04,1141 v5(7516.3,1141)
  Top Layer w30: v5(7516.3,1141) v5(7567.48,1141)
  MidLayer2 w50: PING_OFF.2@6243,1281 6107,1145 v6(6107,762) v6(6107,712) 6127,692 6985,692 7006,671 7268,671 7454,857 7454,1074.87 7516.3,1137.17 v5(7516.3,1141) v5(7567.48,1141)
  Bottom Layer w20: TEST_PORT.4@4588,5027 4588,4995 4603,4980 4666,4980 4703,5017 4703,5179 4743,5219 7194,5219 7666,4747 7666,3130 7650,3114 C85.2@7622,3114 C85.2@7625,3111 ; R273.2@6106.56,1251 6157,1251 6187,1281 PING_OFF.2@6233,1281 ; Q56.2@6124.4,1178.4 Q56.2@6124.8,1178.4 ; Q56.2@6124.8,1178 Q56.2@6124.8,1178.4 ; C16.1@6205,1168 C16.1@6191,1168 6162,1168 6151.6,1178.4 Q56.2@6124.8,1178.4 ; PING_OFF.2@6243,1281 6243,1319 6270,1346 6364,1346 6393.63,1375.63 U16.3@6393.63,1405
  Bottom Layer w25: D49.2@6111.14,824.6 D49.1@6111.14,899.4
  Bottom Layer w30: v6(6107,712) v6(6107,762) ; v6@6107.6,762.6 v6(6107,762) ; D49.2@6111.14,824.6 6111.14,795.14 6107,791 v6(6107,762) ; C16.1@6205,1168 6205,1202 6243,1240 PING_OFF.2@6243,1281 ; v5(7516.3,1141) v5(7567.48,1141) ; 7567,3065 L4.2@7567,3114.01 C85.2@7622,3114
  Bottom Layer w50: 7567,3065 7718,2914 7718,1222.58 7636.42,1141 v5(7567.48,1141)
-5V2: C76.1 R134.1 U18.32 | length 458.2
  MidLayer2 w20: v1@7591.42,1770 v1(7592.42,1770)
  Bottom Layer w10: U18.32@7274.55,1606.4 7371.02,1606.4 7393.42,1584 R134.1@7412.42,1584 C76.1@7478.42,1584 7478.42,1616.54 7500.87,1639 7514.42,1639 7522.42,1647 7522.42,1705 7587.42,1770 v1(7592.42,1770)
AGND: C2.2 C7.2 C9.2 C12.2 C71.2 C76.2 C182.2 C192.2 C205.2 C237.2 C249.2 NT3.1 Q41.2 R17.1 R18.1 R31.2 R32.2 R33.2 R137.1 R280.2 R303.1 R304.1 U2.5 U2.23 U2.49 U18.5 U18.23 U18.49 | length 2573.7
  Top Layer w10: U2.23@7006.84,1547.34 7052.11,1547.34 v15(7140.69,1635.92) 7170.22,1665.45 U2.5@7170.22,1769.78
  Top Layer w20: v1(6698.42,1385) 6730.01,1385 R18.1@6730.35,1384.65 6730.86,1385.16 C182.2@6730.86,1433 v1(6698.42,1433) ; R17.1@6729.42,1326.65 6733.35,1330.59 R18.1@6733.35,1374.65 ; v3(7042.97,600.65) R31.2@7084.85,600.65 ; v3@7063.86,776.44 7076.3,788.88 C7.2@7103.83,788.88 C237.2@7151.91,788.88 ; R33.2@7104.85,682.65 R32.2@7104.86,731 ; C9.2@7110.41,1315.54 7110.41,1287 7124.3,1273.12 7136.2,1273.12 ; C12.2@7136.2,1224.99 7136.2,1273.12 ; v3(7191.09,1288) v3(7151.09,1288) 7136.2,1273.12 ; R137.1@7330.98,1991 7330.98,2034.04 7329.01,2036.01 7354.42,2036.01 7361.42,2043 7361.42,2085.78 v3@7364.41,2088.77 ; v3(7364.41,2094.77) 7364.41,2123.41 7380,2139 R303.1@7380,2165.88 ; C71.2@7525.41,1718.65 7554.07,1718.65 7565.42,1730 7591.42,1730 v3(7591.42,1720) v3@7591.42,1690 ; v1(7552.2,1497.77) v3@7602.2,1497.77 ; C2.2@7555.42,963.12 v5(7555.42,1015) ; v5@7573.2,1294 7575.42,1296.21 v5(7575.42,1349.33)
  Top Layer w25: v3(7042.97,549.47) v3(7042.97,600.65) ; v3@7063.86,776.44 v3(7063.86,731) R32.2@7104.86,731 ; v5(7312.42,386.82) v5(7312.42,438) ; v5(7555.42,1015) v5(7555.42,1066.18)
  Top Layer w30: C249.2@7312.98,490 C249.2@7313.53,489.44 ; v5@7313.53,438 C249.2@7313.53,489.44 ; C205.2@7362.42,489.44 C249.2@7313.53,489.44 ; R280.2@7491.53,1294 R280.2@7492.53,1294 v5@7573.2,1294
  Bottom Layer w10: U18.5@7006.84,1606.4 7111.17,1606.4 v15(7140.69,1635.92) 7229.28,1724.51 U18.23@7229.28,1769.78
  Bottom Layer w20: R304.1@6900,1030.44 6941.86,1030.44 v3(6942.42,1031) 6988.42,1031 6990.42,1029 v3(6992.42,1031) ; C192.2@7364.41,2053.77 v3(7364.41,2094.77) 7414.41,2094.77 7414.19,2095 v3(7410.42,2095) ; C76.2@7558.42,1584 7560.42,1582 7560.42,1534 7552.2,1525.78 v1(7552.2,1497.77) v3@7602.2,1497.77 ; C76.2@7558.42,1587 7558.42,1647 v3(7591.42,1680) v3(7591.42,1720)
  Bottom Layer w25: v5(7555.42,1015) v5(7555.42,1066.18)
  other v3: 7063.86,782.18 7602.2,1496.77
  other v5: 7575.42,1295
  other v15: 7089.51,1584.74 7140.69,1584.74 7191.87,1584.74 7089.51,1635.92 7191.87,1635.92 7089.51,1687.11 7140.69,1687.11 7191.87,1687.11
AUX_: C78.1 R128.2 RT1.2 RT2.1 TEST_PORT.19 U18.25 | length 7618.8
  Top Layer w20: TEST_PORT.19@4188,5127 4188,5171 4250,5233 7288,5233 v4(7308,5213)
  MidLayer2 w20: v4(7308,5213) 7308,5050.13 7457.63,4900.5 7531.63,4900.5 7621.42,4810.72 7621.42,3868.42 7531.5,3778.5 7531.37,3778.5 7513.5,3760.63 7513.5,3760.5 7455,3702 7455,3634.95 7329,3508.95 7329,3318.95 7317.42,3307.36 7317.42,3057.4 7361.82,3013 7452,3013 7570.42,2894.58 RT2.1@7570.42,2771 7530,2771 7391.42,2632.42 7391.42,2174 7456.42,2109 v3(7456.42,2012)
  Bottom Layer w10: U18.25@7274.55,1744.19 7294.61,1744.19 7389.42,1839 7402.42,1839 7429.82,1866.4 7429.82,1985.4 v3(7456.42,2012) 7463.42,2019 7463.42,2118 7439.53,2141.88 R128.2@7439.53,2172
  Bottom Layer w20: R128.2@7439.53,2172 C78.1@7439.53,2220 RT1.2@7439.53,2275
AUXTH_: C79.1 R139.2 R140.1 TEST_PORT.20 U18.24 | length 7238.2
  MidLayer2 w20: v7(7297.77,2267.77) 7297.77,3009.23 7270,3037 7270,3325 7283,3338 7283,3528 7401.5,3646.5 7401.5,3827.63 7506,3932.13 7506,4176 7485,4197 7485,4662 7554,4731 v1(7554,4746)
  MidLayer3 w20: TEST_PORT.20@4188,5027 4188,4977 4222,4943 4583.02,4943 4590.02,4950 4687.6,4950 4753.59,5015.99 4846.49,5015.99 4864.1,5033.6 4893.1,5033.6 4910.7,5015.99 5470.41,5015.99 5659.4,4827 5845.5,4827 5931.5,4913 6092,4913 6126,4879 6693.91,4879 6739.41,4833.5 6858.5,4833.5 6874,4849 7063.15,4849 7086,4871.85 7086,4872 7265.59,4872 7280.59,4887 7519,4887 7554,4852 v1(7554,4746)
  Bottom Layer w10: U18.24@7248.96,1769.78 7290.06,1769.78 7377.28,1857 7394.25,1857 7411.82,1874.57 7411.82,2049.75 7444.41,2082.35 7444.41,2107.2 7426.61,2125 7380.42,2125 7340.42,2165 7340.42,2233.48 7328.95,2244.94 C79.1@7328.95,2267.77
  Bottom Layer w20: v7(7297.77,2267.77) C79.1@7328.95,2267.77 7328.95,2290.46 7320.42,2298.99 7320.42,2323 7319.98,2323.44 R140.1@7319.98,2394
